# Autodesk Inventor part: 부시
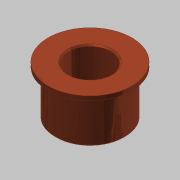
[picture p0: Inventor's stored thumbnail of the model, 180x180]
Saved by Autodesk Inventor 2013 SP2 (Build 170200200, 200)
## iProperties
Created: 2015-10
Part Number: 부시
Document SubType Name: Modeling
Designer: mdu
Density: 7.86 g/cm^3
Material: 강철, 연강
Mass: 246.97 g
Surface Area: 129.264 cm^2
Volume: 31.4212 cm^3
Author: mdu
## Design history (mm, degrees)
sketch "스케치1"
  geometry: C1 r 31 at (0, 0) reference; C2 r 25 at (0, 0) reference; C3 r 30 at (0, 0) reference; 1 further point
  node "참조1"
  node "참조2"
  node "참조4"
extrude "돌출1" new body sketch "스케치1" distance "d0" = 3; taper "d1" = 0 deg
extrude "돌출2" join sketch "스케치1" distance "d2" = 35; taper "d3" = 0 deg
chamfer "모따기1" distance "d6" = 1; stored, may be unused: second distance "d7" = 2, angle "d8" = 45 deg
sketch "스케치3"
  geometry: C1 r 15 at (0, 0); 1 further point
  constraints: 1 centre point, 1 coincident
  dimensions: "d13" = 30 diameter of C1
extrude "돌출4" cut sketch "스케치3" stored distance "d14" = 10; taper "d15" = 0 deg
chamfer "모따기3" distance "d16" = 1; stored, may be unused: second distance "d17" = 2, angle "d18" = 45 deg
node "솔리드1"
